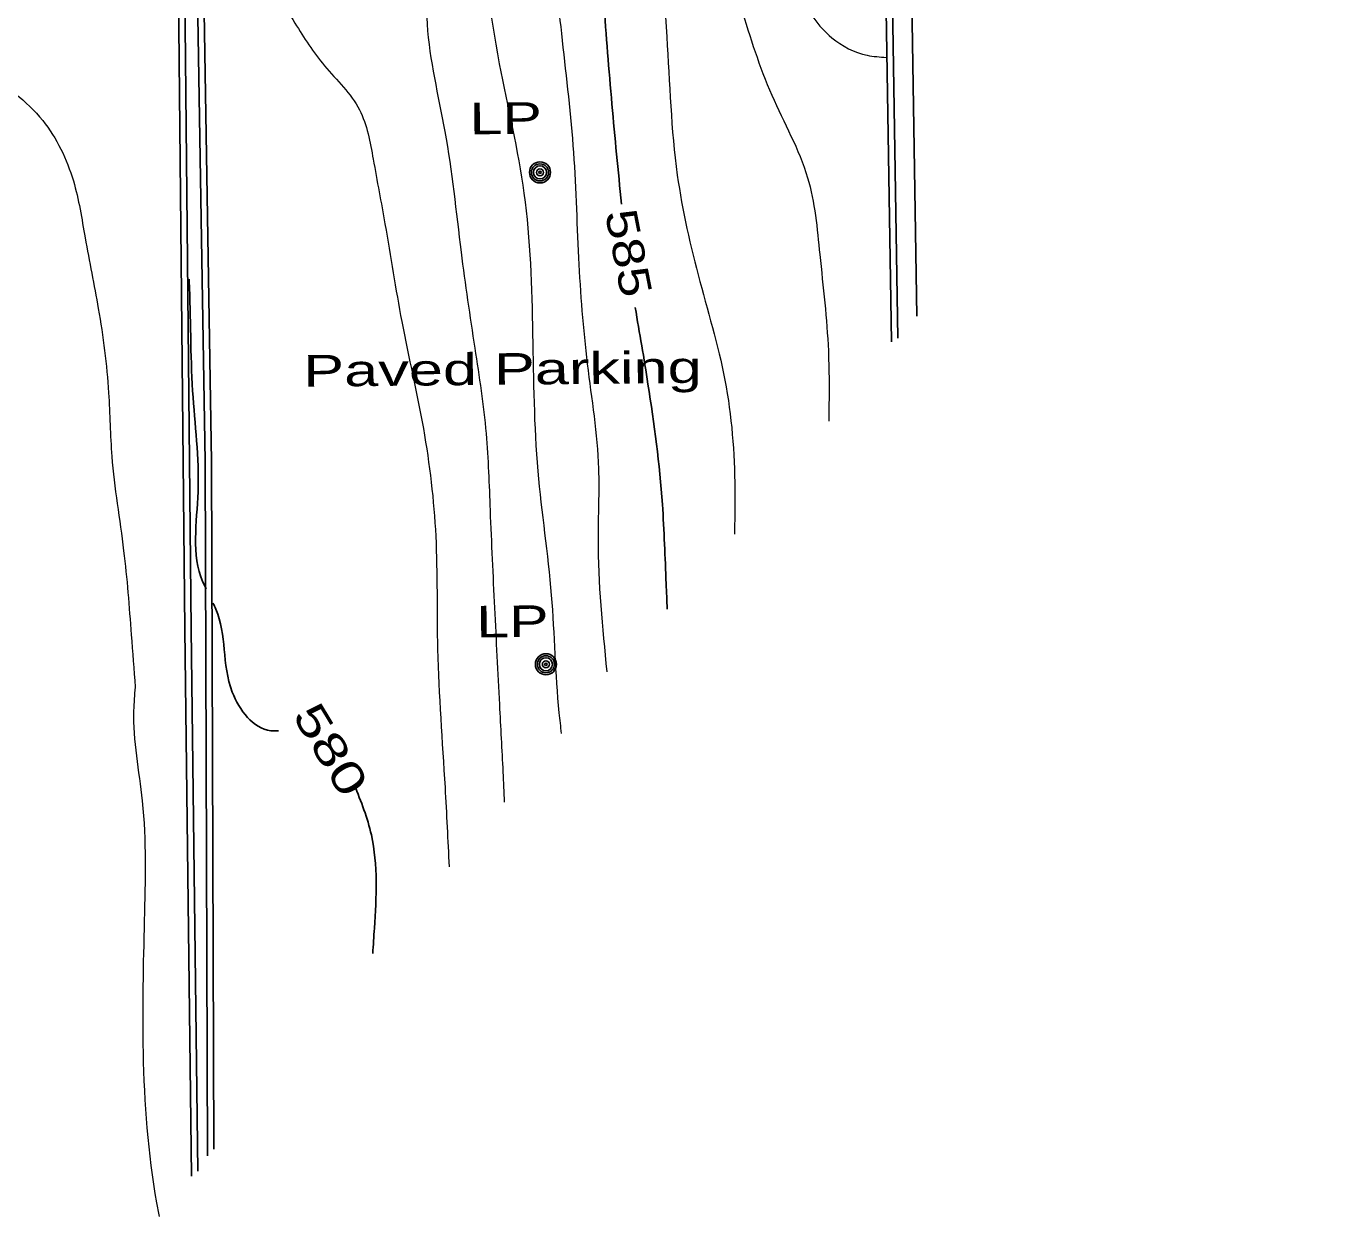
# Model space of a CAD drawing. Extents: x 2361708 to 2370558, y 6977955 to 6991887.
# Drawn here: x 2369362.7 to 2369563, y 6989903.4 to 6990084.2 of the extents above; entities that cross this region are included whole.
import ezdxf
from ezdxf.enums import TextEntityAlignment as Align

# ---------------------------------------------------------------- set-up
doc = ezdxf.new("R2010")
doc.units = 0
doc.header["$LTSCALE"] = 1.9
for name, color, linetype, lineweight in [('11', 7, 'Continuous', 25), ('2', 7, 'Continuous', 25), ('20', 7, 'Continuous', 25), ('31', 7, 'Continuous', 13), ('35', 7, 'Continuous', 13)]:
    doc.layers.add(name, color=color, linetype=linetype, lineweight=lineweight)

msp = doc.modelspace()

# ---------------------------------------------------------------- linework, layer by layer
at = {"layer": '11'}
msp.add_lwpolyline([(2369562.985, 6990117.751), (2369561.473, 6990213.631), (2369495.25, 6990212.591), (2369497.97, 6990040.208)], dxfattribs=at)
at = {"layer": '2'}
for points in [[(2369495.25, 6990212.591), (2369491.31, 6990212.524), (2369494.137, 6990036.311)], [(2369495.269, 6990211.631), (2369492.289, 6990211.583), (2369495.092, 6990036.861)], [(2369391.151, 6989913.586), (2369390.805, 6990018.117), (2369389.199, 6990117.477), (2369313.54, 6990117.067), (2369175.577, 6990116.714), (2369175.632, 6990125.554), (2369173.803, 6990125.457)], [(2369390.2, 6989912.606), (2369389.845, 6990018.108), (2369388.259, 6990116.508), (2369385.989, 6990116.497)], [(2369369.23, 6990097.326), (2369382.794, 6990103.295), (2369386.718, 6990094.552), (2369387.728, 6989992.627), (2369388.752, 6989910.242)], [(2369369.619, 6990096.449), (2369382.306, 6990102.031), (2369385.76, 6990094.343), (2369386.768, 6989992.617), (2369387.799, 6989909.484)]]:
    msp.add_lwpolyline(points, dxfattribs=at)
at = {"layer": '20'}
for centre, radius in [((2369440.73, 6990062.035), 1.6), ((2369440.73, 6990062.035), 1.3), ((2369440.73, 6990062.035), 1), ((2369440.73, 6990062.035), 0.539), ((2369440.73, 6990062.035), 0.192), ((2369441.631, 6989987.29), 1.6), ((2369441.631, 6989987.29), 1.3), ((2369441.631, 6989987.29), 1), ((2369441.631, 6989987.29), 0.539), ((2369441.631, 6989987.29), 0.192)]:
    msp.add_circle(centre, radius, dxfattribs=at)
at = {"layer": '31', "lineweight": 25}
for points in [[(2369425.756, 6990274.592), (2369429.071, 6990265.714), (2369431.897, 6990255.58), (2369435.594, 6990246.485), (2369438.225, 6990237.909), (2369438.806, 6990234.665), (2369436.175, 6990228.469), (2369433.054, 6990219.139), (2369434.738, 6990207.205), (2369437.799, 6990196.503), (2369438.675, 6990187.561), (2369440.424, 6990175.107), (2369442.114, 6990163.523), (2369444.181, 6990153.332), (2369445.773, 6990141.537), (2369447.164, 6990130.95), (2369448.276, 6990117.039), (2369449.535, 6990101.51), (2369450.423, 6990088.058), (2369451.662, 6990072.399), (2369453.106, 6990057.212)], [(2369387.432, 6990045.797), (2369387.445, 6990045.497), (2369387.953, 6990028.831), (2369388.779, 6990013.498), (2369389.52, 6989999.784), (2369390.019, 6989998.739)], [(2369455.195, 6990041.511), (2369457.137, 6990029.87), (2369459.321, 6990011.589), (2369459.896, 6989999.514), (2369460.062, 6989995.666)], [(2369391.04, 6989996.589), (2369391.479, 6989995.663), (2369393.979, 6989983.076), (2369399.825, 6989977.201), (2369401.006, 6989977.152)], [(2369412.544, 6989968.932), (2369415.107, 6989961.356), (2369415.572, 6989947.18), (2369415.308, 6989943.327)]]:
    msp.add_spline(points, degree=3, dxfattribs=at)
at = {"layer": '35'}
for points in [[(2369427.813, 6990429.3), (2369426.317, 6990412.075), (2369424.58, 6990383.426), (2369426.735, 6990361.916), (2369428.134, 6990335.728), (2369429.465, 6990315.64), (2369430.629, 6990300.51), (2369432.606, 6990286.198), (2369435.671, 6990276.157), (2369439.19, 6990266.87), (2369442.297, 6990255.609), (2369446.21, 6990244.876), (2369450.612, 6990235.227), (2369451.116, 6990230.582), (2369446.008, 6990221.913), (2369444.572, 6990210.978), (2369445.798, 6990203.04), (2369448.261, 6990192.183), (2369450.238, 6990179.971), (2369451.617, 6990164.283), (2369452.35, 6990147.149), (2369454.267, 6990125.387), (2369457.314, 6990106.825), (2369459.995, 6990082.619), (2369461.595, 6990061.614), (2369465.029, 6990045.455), (2369469.011, 6990029.442), (2369470.339, 6990012.834), (2369470.284, 6990007.083)], [(2369437.929, 6990419.255), (2369438.121, 6990403.347), (2369438.002, 6990373.864), (2369438.25, 6990344.555), (2369440.81, 6990321.438), (2369441.942, 6990296.108), (2369446.681, 6990280.422), (2369451.019, 6990267.062), (2369459.409, 6990256.532), (2369462.036, 6990245.346), (2369466.975, 6990237.053), (2369468.33, 6990231.345), (2369462.699, 6990223.992), (2369456.44, 6990215.472), (2369456.224, 6990206.629), (2369459, 6990192.355), (2369460.08, 6990174.484), (2369461.35, 6990156.596), (2369462.738, 6990137.888), (2369464.314, 6990115.262), (2369467.151, 6990100.938), (2369471.263, 6990087.056), (2369475.94, 6990073.781), (2369481.379, 6990061.232), (2369483.241, 6990049.549), (2369484.54, 6990034.9), (2369484.611, 6990024.241)], [(2369450.809, 6990406.727), (2369450.967, 6990394.318), (2369451.081, 6990371.928), (2369450.638, 6990350.153), (2369451.2, 6990331.997), (2369451.951, 6990321.484), (2369454.011, 6990305.723), (2369455.828, 6990294.489), (2369459.744, 6990284.377), (2369465.882, 6990275.164), (2369473.37, 6990263.885), (2369479.351, 6990255.432), (2369484.048, 6990242.086), (2369489.578, 6990233.698), (2369487.457, 6990228.597), (2369481.896, 6990225.525), (2369473.967, 6990220.099), (2369471.248, 6990210.542), (2369470.52, 6990199.775), (2369471.095, 6990187.7), (2369471.914, 6990173.187), (2369472.747, 6990154.934), (2369474.689, 6990134.792), (2369475.348, 6990116.957), (2369476.573, 6990100.738), (2369480.216, 6990088.942), (2369485.077, 6990082.498), (2369490.433, 6990079.828), (2369493.366, 6990079.516)], [(2369386.446, 6990293.349), (2369390.986, 6990288.102), (2369397.935, 6990281.868), (2369403.492, 6990280.091), (2369411.4, 6990279.366), (2369414.313, 6990274.833), (2369416.263, 6990267.502), (2369418.571, 6990257.193), (2369422.196, 6990248.357), (2369424.447, 6990236.668), (2369424.825, 6990226.302), (2369424.841, 6990214.181), (2369427.202, 6990201.502), (2369428.984, 6990187.589), (2369430.93, 6990172.247), (2369434.739, 6990156.662), (2369436.536, 6990144.369), (2369439.467, 6990127.386), (2369441.251, 6990115.462), (2369442.548, 6990099.034), (2369443.979, 6990083.147), (2369445.741, 6990066.123), (2369446.584, 6990049.039), (2369447.917, 6990032.932), (2369449.619, 6990016.997), (2369449.55, 6990006.326), (2369450.883, 6989986.158)], [(2369386.857, 6990238.58), (2369393.529, 6990234.234), (2369402.551, 6990228.74), (2369409.981, 6990222.53), (2369413.027, 6990217.658), (2369414.5, 6990206.882), (2369417.212, 6990193.027), (2369419.943, 6990177.112), (2369423.105, 6990161.202), (2369427.44, 6990144.972), (2369430.264, 6990124.618), (2369431.422, 6990102.748), (2369434.552, 6990078.536), (2369438.3, 6990058.861), (2369439.604, 6990037.423), (2369440.402, 6990016.65), (2369442.451, 6989997.778), (2369443.612, 6989979.888), (2369443.962, 6989976.781)], [(2369387.602, 6990193.865), (2369393.14, 6990188.848), (2369399.657, 6990180.869), (2369404.572, 6990169.776), (2369411.389, 6990164.89), (2369414.87, 6990156.453), (2369417.371, 6990145.857), (2369419.149, 6990135.473), (2369421.144, 6990116.101), (2369423.506, 6990100.213), (2369423.574, 6990084.563), (2369426.27, 6990068.267), (2369428.745, 6990049.92), (2369430.823, 6990035.329), (2369432.537, 6990022.345), (2369433.148, 6990010.69), (2369433.819, 6989995.856), (2369434.569, 6989981.162), (2369435.097, 6989970.906), (2369435.311, 6989966.329)], [(2369329.751, 6990112.831), (2369330.813, 6990107.361), (2369336.376, 6990098.623), (2369342.271, 6990088.719), (2369348.956, 6990081.972), (2369356.19, 6990077.361), (2369365.171, 6990069.906), (2369369.828, 6990060.75), (2369371.621, 6990052.086), (2369373.623, 6990041.335), (2369375.195, 6990028.529), (2369375.677, 6990018.883), (2369377.474, 6990004.55), (2369378.626, 6989991.78), (2369379.222, 6989983.815)], [(2369389.411, 6990094.168), (2369396.499, 6990094.405), (2369400.728, 6990089.316), (2369403.502, 6990084.701), (2369408.004, 6990078.234), (2369413.298, 6990071.544), (2369415.389, 6990064.034), (2369417.173, 6990054.2), (2369419.735, 6990039.364), (2369423.009, 6990023.094), (2369424.885, 6990006.741), (2369425.168, 6989989.603), (2369426.299, 6989968.583), (2369426.913, 6989956.518)], [(2369379.222, 6989983.815), (2369378.985, 6989980.243), (2369380.286, 6989966.525), (2369380.609, 6989948.387), (2369380.42, 6989928.274), (2369382.467, 6989905.472), (2369382.857, 6989903.356)]]:
    msp.add_spline(points, degree=3, dxfattribs=at)

# ---------------------------------------------------------------- texts
at = {"layer": '2', "width": 1.45}
msp.add_text('Paved Parking', height=4.8, rotation=0.545, dxfattribs=at).set_placement((2369404.788, 6990029.471))
at = {"layer": '20', "width": 1.4}
for p in [(2369425.054, 6990067.766), (2369426.072, 6989991.312)]:
    msp.add_text('  LP', height=4.8, rotation=0.545, dxfattribs=at).set_placement(p)
at = {"layer": '31'}
for s, rotation, width, p in [(' 585 ', 281.033, 1.25, (2369451.857, 6990049.35)), (' 580 ', 301.158, 1.4, (2369406.885, 6989973.097))]:
    msp.add_text(s, height=4.8, rotation=rotation, dxfattribs=dict(at, width=width)).set_placement(p, align=Align.CENTER)

doc.saveas('drawing.dxf')
